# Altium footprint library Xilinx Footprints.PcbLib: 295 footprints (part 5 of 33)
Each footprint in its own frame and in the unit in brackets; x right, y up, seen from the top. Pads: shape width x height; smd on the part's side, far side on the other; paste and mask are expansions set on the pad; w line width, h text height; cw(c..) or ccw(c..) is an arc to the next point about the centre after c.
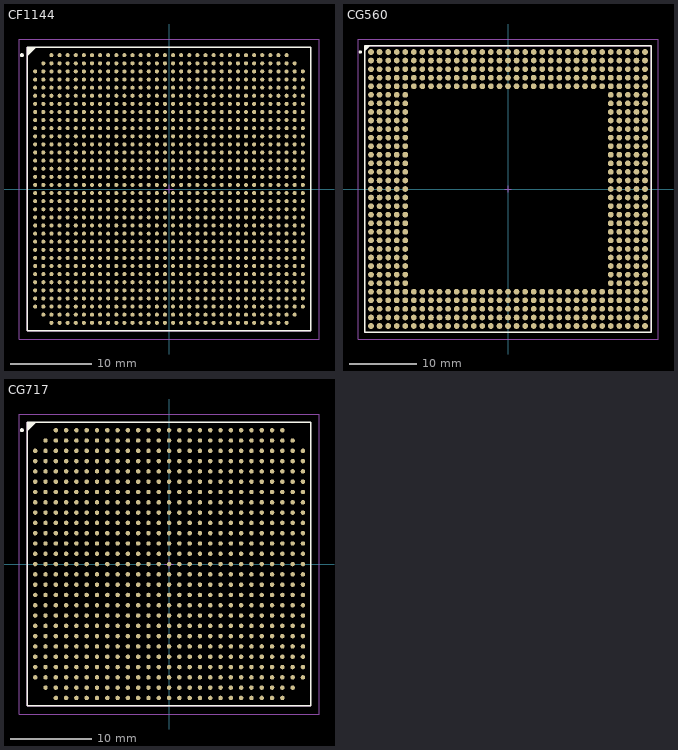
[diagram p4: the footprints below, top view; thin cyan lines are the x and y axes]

## CF1144 [mm] "1156-Pin Ceramic Column Grid Array 1 mm Pitch"
height 7
pads (1144):
  round 0.5 smd: A3(-14.5,16.5) A4(-13.5,16.5) A5(-12.5,16.5) A6(-11.5,16.5) A7(-10.5,16.5) A8(-9.5,16.5) A9(-8.5,16.5) A10(-7.5,16.5) A11(-6.5,16.5) A12(-5.5,16.5) A13(-4.5,16.5) A14(-3.5,16.5) A15(-2.5,16.5) A16(-1.5,16.5) A17(-0.5,16.5) A18(0.5,16.5) A19(1.5,16.5) A20(2.5,16.5) A21(3.5,16.5) A22(4.5,16.5) A23(5.5,16.5) A24(6.5,16.5) A25(7.5,16.5) A26(8.5,16.5) A27(9.5,16.5) A28(10.5,16.5) A29(11.5,16.5) A30(12.5,16.5) A31(13.5,16.5) A32(14.5,16.5) AA1(-16.5,-3.5) AA2(-15.5,-3.5) AA3(-14.5,-3.5) AA4(-13.5,-3.5) AA5(-12.5,-3.5) AA6(-11.5,-3.5) AA7(-10.5,-3.5) AA8(-9.5,-3.5) AA9(-8.5,-3.5) AA10(-7.5,-3.5) AA11(-6.5,-3.5) AA12(-5.5,-3.5) AA13(-4.5,-3.5) AA14(-3.5,-3.5) AA15(-2.5,-3.5) AA16(-1.5,-3.5) AA17(-0.5,-3.5) AA18(0.5,-3.5) AA19(1.5,-3.5) AA20(2.5,-3.5) AA21(3.5,-3.5) AA22(4.5,-3.5) AA23(5.5,-3.5) AA24(6.5,-3.5) AA25(7.5,-3.5) AA26(8.5,-3.5) AA27(9.5,-3.5) AA28(10.5,-3.5) AA29(11.5,-3.5) AA30(12.5,-3.5) AA31(13.5,-3.5) AA32(14.5,-3.5) AA33(15.5,-3.5) AA34(16.5,-3.5) AB1(-16.5,-4.5) AB2(-15.5,-4.5) AB3(-14.5,-4.5) AB4(-13.5,-4.5) AB5(-12.5,-4.5) AB6(-11.5,-4.5) AB7(-10.5,-4.5) AB8(-9.5,-4.5) AB9(-8.5,-4.5) AB10(-7.5,-4.5) AB11(-6.5,-4.5) AB12(-5.5,-4.5) AB13(-4.5,-4.5) AB14(-3.5,-4.5) AB15(-2.5,-4.5) AB16(-1.5,-4.5) AB17(-0.5,-4.5) AB18(0.5,-4.5) AB19(1.5,-4.5) AB20(2.5,-4.5) AB21(3.5,-4.5) AB22(4.5,-4.5) AB23(5.5,-4.5) AB24(6.5,-4.5) AB25(7.5,-4.5) AB26(8.5,-4.5) AB27(9.5,-4.5) AB28(10.5,-4.5) AB29(11.5,-4.5) AB30(12.5,-4.5) AB31(13.5,-4.5) AB32(14.5,-4.5) AB33(15.5,-4.5) AB34(16.5,-4.5) AC1(-16.5,-5.5) AC2(-15.5,-5.5) AC3(-14.5,-5.5) AC4(-13.5,-5.5) AC5(-12.5,-5.5) AC6(-11.5,-5.5) AC7(-10.5,-5.5) AC8(-9.5,-5.5) AC9(-8.5,-5.5) AC10(-7.5,-5.5) AC11(-6.5,-5.5) AC12(-5.5,-5.5) AC13(-4.5,-5.5) AC14(-3.5,-5.5) AC15(-2.5,-5.5) AC16(-1.5,-5.5) AC17(-0.5,-5.5) AC18(0.5,-5.5) AC19(1.5,-5.5) AC20(2.5,-5.5) AC21(3.5,-5.5) AC22(4.5,-5.5) AC23(5.5,-5.5) AC24(6.5,-5.5) AC25(7.5,-5.5) AC26(8.5,-5.5) AC27(9.5,-5.5) AC28(10.5,-5.5) AC29(11.5,-5.5) AC30(12.5,-5.5) AC31(13.5,-5.5) AC32(14.5,-5.5) AC33(15.5,-5.5) AC34(16.5,-5.5) AD1(-16.5,-6.5) AD2(-15.5,-6.5) AD3(-14.5,-6.5) AD4(-13.5,-6.5) AD5(-12.5,-6.5) AD6(-11.5,-6.5) AD7(-10.5,-6.5) AD8(-9.5,-6.5) AD9(-8.5,-6.5) AD10(-7.5,-6.5) AD11(-6.5,-6.5) AD12(-5.5,-6.5) AD13(-4.5,-6.5) AD14(-3.5,-6.5) AD15(-2.5,-6.5) AD16(-1.5,-6.5) AD17(-0.5,-6.5) AD18(0.5,-6.5) AD19(1.5,-6.5) AD20(2.5,-6.5) AD21(3.5,-6.5) AD22(4.5,-6.5) AD23(5.5,-6.5) AD24(6.5,-6.5) AD25(7.5,-6.5) AD26(8.5,-6.5) AD27(9.5,-6.5) AD28(10.5,-6.5) AD29(11.5,-6.5) AD30(12.5,-6.5) AD31(13.5,-6.5) AD32(14.5,-6.5) AD33(15.5,-6.5) AD34(16.5,-6.5) AE1(-16.5,-7.5) AE2(-15.5,-7.5) AE3(-14.5,-7.5) AE4(-13.5,-7.5) AE5(-12.5,-7.5) AE6(-11.5,-7.5) AE7(-10.5,-7.5) AE8(-9.5,-7.5) AE9(-8.5,-7.5) AE10(-7.5,-7.5) AE11(-6.5,-7.5) AE12(-5.5,-7.5) AE13(-4.5,-7.5) AE14(-3.5,-7.5) AE15(-2.5,-7.5) AE16(-1.5,-7.5) AE17(-0.5,-7.5) AE18(0.5,-7.5) AE19(1.5,-7.5) AE20(2.5,-7.5) AE21(3.5,-7.5) AE22(4.5,-7.5) AE23(5.5,-7.5) AE24(6.5,-7.5) AE25(7.5,-7.5) AE26(8.5,-7.5) AE27(9.5,-7.5) AE28(10.5,-7.5) AE29(11.5,-7.5) AE30(12.5,-7.5) AE31(13.5,-7.5) AE32(14.5,-7.5) AE33(15.5,-7.5) AE34(16.5,-7.5) AF1(-16.5,-8.5) AF2(-15.5,-8.5) AF3(-14.5,-8.5) AF4(-13.5,-8.5) AF5(-12.5,-8.5) AF6(-11.5,-8.5) AF7(-10.5,-8.5) AF8(-9.5,-8.5) AF9(-8.5,-8.5) AF10(-7.5,-8.5) AF11(-6.5,-8.5) AF12(-5.5,-8.5) AF13(-4.5,-8.5) AF14(-3.5,-8.5) AF15(-2.5,-8.5) AF16(-1.5,-8.5) AF17(-0.5,-8.5) AF18(0.5,-8.5) AF19(1.5,-8.5) AF20(2.5,-8.5) AF21(3.5,-8.5) AF22(4.5,-8.5) AF23(5.5,-8.5) AF24(6.5,-8.5) AF25(7.5,-8.5) AF26(8.5,-8.5) AF27(9.5,-8.5) AF28(10.5,-8.5) AF29(11.5,-8.5) AF30(12.5,-8.5) AF31(13.5,-8.5) AF32(14.5,-8.5) AF33(15.5,-8.5) AF34(16.5,-8.5) AG1(-16.5,-9.5) AG2(-15.5,-9.5) AG3(-14.5,-9.5) AG4(-13.5,-9.5) AG5(-12.5,-9.5) AG6(-11.5,-9.5) AG7(-10.5,-9.5) AG8(-9.5,-9.5) AG9(-8.5,-9.5) AG10(-7.5,-9.5) AG11(-6.5,-9.5) AG12(-5.5,-9.5) AG13(-4.5,-9.5) AG14(-3.5,-9.5) AG15(-2.5,-9.5) AG16(-1.5,-9.5) AG17(-0.5,-9.5) AG18(0.5,-9.5) AG19(1.5,-9.5) AG20(2.5,-9.5) AG21(3.5,-9.5) AG22(4.5,-9.5) AG23(5.5,-9.5) AG24(6.5,-9.5) AG25(7.5,-9.5) AG26(8.5,-9.5) AG27(9.5,-9.5) AG28(10.5,-9.5) AG29(11.5,-9.5) AG30(12.5,-9.5) AG31(13.5,-9.5) AG32(14.5,-9.5) AG33(15.5,-9.5) AG34(16.5,-9.5) AH1(-16.5,-10.5) AH2(-15.5,-10.5) AH3(-14.5,-10.5) AH4(-13.5,-10.5) AH5(-12.5,-10.5) AH6(-11.5,-10.5) AH7(-10.5,-10.5) AH8(-9.5,-10.5) AH9(-8.5,-10.5) AH10(-7.5,-10.5) AH11(-6.5,-10.5) AH12(-5.5,-10.5) AH13(-4.5,-10.5) AH14(-3.5,-10.5) AH15(-2.5,-10.5) AH16(-1.5,-10.5) AH17(-0.5,-10.5) AH18(0.5,-10.5) AH19(1.5,-10.5) AH20(2.5,-10.5) AH21(3.5,-10.5) AH22(4.5,-10.5) AH23(5.5,-10.5) AH24(6.5,-10.5) AH25(7.5,-10.5) AH26(8.5,-10.5) AH27(9.5,-10.5) AH28(10.5,-10.5) AH29(11.5,-10.5) AH30(12.5,-10.5) AH31(13.5,-10.5) AH32(14.5,-10.5) AH33(15.5,-10.5) AH34(16.5,-10.5) AJ1(-16.5,-11.5) AJ2(-15.5,-11.5) AJ3(-14.5,-11.5) AJ4(-13.5,-11.5) AJ5(-12.5,-11.5) AJ6(-11.5,-11.5) AJ7(-10.5,-11.5) AJ8(-9.5,-11.5) AJ9(-8.5,-11.5) AJ10(-7.5,-11.5) AJ11(-6.5,-11.5) AJ12(-5.5,-11.5) AJ13(-4.5,-11.5) AJ14(-3.5,-11.5) AJ15(-2.5,-11.5) AJ16(-1.5,-11.5) AJ17(-0.5,-11.5) AJ18(0.5,-11.5) AJ19(1.5,-11.5) AJ20(2.5,-11.5) AJ21(3.5,-11.5) AJ22(4.5,-11.5) AJ23(5.5,-11.5) AJ24(6.5,-11.5) AJ25(7.5,-11.5) AJ26(8.5,-11.5) AJ27(9.5,-11.5) AJ28(10.5,-11.5) AJ29(11.5,-11.5) AJ30(12.5,-11.5) AJ31(13.5,-11.5) AJ32(14.5,-11.5) AJ33(15.5,-11.5) AJ34(16.5,-11.5) AK1(-16.5,-12.5) AK2(-15.5,-12.5) AK3(-14.5,-12.5) AK4(-13.5,-12.5) AK5(-12.5,-12.5) AK6(-11.5,-12.5) AK7(-10.5,-12.5) AK8(-9.5,-12.5) AK9(-8.5,-12.5) AK10(-7.5,-12.5) AK11(-6.5,-12.5) AK12(-5.5,-12.5) AK13(-4.5,-12.5) AK14(-3.5,-12.5) AK15(-2.5,-12.5) AK16(-1.5,-12.5) AK17(-0.5,-12.5) AK18(0.5,-12.5) AK19(1.5,-12.5) AK20(2.5,-12.5) AK21(3.5,-12.5) AK22(4.5,-12.5) AK23(5.5,-12.5) AK24(6.5,-12.5) AK25(7.5,-12.5) AK26(8.5,-12.5) AK27(9.5,-12.5) AK28(10.5,-12.5) AK29(11.5,-12.5) AK30(12.5,-12.5) AK31(13.5,-12.5) AK32(14.5,-12.5) AK33(15.5,-12.5) AK34(16.5,-12.5) AL1(-16.5,-13.5) AL2(-15.5,-13.5) AL3(-14.5,-13.5) AL4(-13.5,-13.5) AL5(-12.5,-13.5) AL6(-11.5,-13.5) AL7(-10.5,-13.5) AL8(-9.5,-13.5) AL9(-8.5,-13.5) AL10(-7.5,-13.5) AL11(-6.5,-13.5) AL12(-5.5,-13.5) AL13(-4.5,-13.5) AL14(-3.5,-13.5) AL15(-2.5,-13.5) AL16(-1.5,-13.5) AL17(-0.5,-13.5) AL18(0.5,-13.5) AL19(1.5,-13.5) AL20(2.5,-13.5) AL21(3.5,-13.5) AL22(4.5,-13.5) AL23(5.5,-13.5) AL24(6.5,-13.5) AL25(7.5,-13.5) AL26(8.5,-13.5) AL27(9.5,-13.5) AL28(10.5,-13.5) AL29(11.5,-13.5) AL30(12.5,-13.5) AL31(13.5,-13.5) AL32(14.5,-13.5) AL33(15.5,-13.5) AL34(16.5,-13.5) AM1(-16.5,-14.5) AM2(-15.5,-14.5) AM3(-14.5,-14.5) AM4(-13.5,-14.5) AM5(-12.5,-14.5) AM6(-11.5,-14.5) AM7(-10.5,-14.5) AM8(-9.5,-14.5) AM9(-8.5,-14.5) AM10(-7.5,-14.5) AM11(-6.5,-14.5) AM12(-5.5,-14.5) AM13(-4.5,-14.5) AM14(-3.5,-14.5) AM15(-2.5,-14.5) AM16(-1.5,-14.5) AM17(-0.5,-14.5) AM18(0.5,-14.5) AM19(1.5,-14.5) AM20(2.5,-14.5) AM21(3.5,-14.5) AM22(4.5,-14.5) AM23(5.5,-14.5) AM24(6.5,-14.5) AM25(7.5,-14.5) AM26(8.5,-14.5) AM27(9.5,-14.5) AM28(10.5,-14.5) AM29(11.5,-14.5) AM30(12.5,-14.5) AM31(13.5,-14.5) AM32(14.5,-14.5) AM33(15.5,-14.5) AM34(16.5,-14.5) AN2(-15.5,-15.5) AN3(-14.5,-15.5) AN4(-13.5,-15.5) AN5(-12.5,-15.5) AN6(-11.5,-15.5) AN7(-10.5,-15.5) AN8(-9.5,-15.5) AN9(-8.5,-15.5) AN10(-7.5,-15.5) AN11(-6.5,-15.5) AN12(-5.5,-15.5) AN13(-4.5,-15.5) AN14(-3.5,-15.5) AN15(-2.5,-15.5) AN16(-1.5,-15.5) AN17(-0.5,-15.5) AN18(0.5,-15.5) AN19(1.5,-15.5) AN20(2.5,-15.5) AN21(3.5,-15.5) AN22(4.5,-15.5) AN23(5.5,-15.5) AN24(6.5,-15.5) AN25(7.5,-15.5) AN26(8.5,-15.5) AN27(9.5,-15.5) AN28(10.5,-15.5) AN29(11.5,-15.5) AN30(12.5,-15.5) AN31(13.5,-15.5) AN32(14.5,-15.5) AN33(15.5,-15.5) AP3(-14.5,-16.5) AP4(-13.5,-16.5) AP5(-12.5,-16.5) AP6(-11.5,-16.5) AP7(-10.5,-16.5) AP8(-9.5,-16.5) AP9(-8.5,-16.5) AP10(-7.5,-16.5) AP11(-6.5,-16.5) AP12(-5.5,-16.5) AP13(-4.5,-16.5) AP14(-3.5,-16.5) AP15(-2.5,-16.5) AP16(-1.5,-16.5) AP17(-0.5,-16.5) AP18(0.5,-16.5) AP19(1.5,-16.5) AP20(2.5,-16.5) AP21(3.5,-16.5) AP22(4.5,-16.5) AP23(5.5,-16.5) AP24(6.5,-16.5) AP25(7.5,-16.5) AP26(8.5,-16.5) AP27(9.5,-16.5) AP28(10.5,-16.5) AP29(11.5,-16.5) AP30(12.5,-16.5) AP31(13.5,-16.5) AP32(14.5,-16.5) B2(-15.5,15.5) B3(-14.5,15.5) B4(-13.5,15.5) B5(-12.5,15.5) B6(-11.5,15.5) B7(-10.5,15.5) B8(-9.5,15.5) B9(-8.5,15.5) B10(-7.5,15.5) B11(-6.5,15.5) B12(-5.5,15.5) B13(-4.5,15.5) B14(-3.5,15.5) B15(-2.5,15.5) B16(-1.5,15.5) B17(-0.5,15.5) B18(0.5,15.5) B19(1.5,15.5) B20(2.5,15.5) B21(3.5,15.5) B22(4.5,15.5) B23(5.5,15.5) B24(6.5,15.5) B25(7.5,15.5) B26(8.5,15.5) B27(9.5,15.5) B28(10.5,15.5) B29(11.5,15.5) B30(12.5,15.5) B31(13.5,15.5) B32(14.5,15.5) B33(15.5,15.5) C1(-16.5,14.5) C2(-15.5,14.5) C3(-14.5,14.5) C4(-13.5,14.5) C5(-12.5,14.5) C6(-11.5,14.5) C7(-10.5,14.5) C8(-9.5,14.5) C9(-8.5,14.5) C10(-7.5,14.5) C11(-6.5,14.5) C12(-5.5,14.5) C13(-4.5,14.5) C14(-3.5,14.5) C15(-2.5,14.5) C16(-1.5,14.5) C17(-0.5,14.5) C18(0.5,14.5) C19(1.5,14.5) C20(2.5,14.5) C21(3.5,14.5) C22(4.5,14.5) C23(5.5,14.5) C24(6.5,14.5) C25(7.5,14.5) C26(8.5,14.5) C27(9.5,14.5) C28(10.5,14.5) C29(11.5,14.5) C30(12.5,14.5) C31(13.5,14.5) C32(14.5,14.5) C33(15.5,14.5) C34(16.5,14.5) D1(-16.5,13.5) D2(-15.5,13.5) D3(-14.5,13.5) D4(-13.5,13.5) D5(-12.5,13.5) D6(-11.5,13.5) D7(-10.5,13.5) D8(-9.5,13.5) D9(-8.5,13.5) D10(-7.5,13.5) D11(-6.5,13.5) D12(-5.5,13.5) D13(-4.5,13.5) D14(-3.5,13.5) D15(-2.5,13.5) D16(-1.5,13.5) D17(-0.5,13.5) D18(0.5,13.5) D19(1.5,13.5) D20(2.5,13.5) D21(3.5,13.5) D22(4.5,13.5) D23(5.5,13.5) D24(6.5,13.5) D25(7.5,13.5) D26(8.5,13.5) D27(9.5,13.5) D28(10.5,13.5) D29(11.5,13.5) D30(12.5,13.5) D31(13.5,13.5) D32(14.5,13.5) D33(15.5,13.5) D34(16.5,13.5) E1(-16.5,12.5) E2(-15.5,12.5) E3(-14.5,12.5) E4(-13.5,12.5) E5(-12.5,12.5) E6(-11.5,12.5) E7(-10.5,12.5) E8(-9.5,12.5) E9(-8.5,12.5) E10(-7.5,12.5) E11(-6.5,12.5) E12(-5.5,12.5) E13(-4.5,12.5) E14(-3.5,12.5) E15(-2.5,12.5) E16(-1.5,12.5) E17(-0.5,12.5) E18(0.5,12.5) E19(1.5,12.5) E20(2.5,12.5) E21(3.5,12.5) E22(4.5,12.5) E23(5.5,12.5) E24(6.5,12.5) E25(7.5,12.5) E26(8.5,12.5) E27(9.5,12.5) E28(10.5,12.5) E29(11.5,12.5) E30(12.5,12.5) E31(13.5,12.5) E32(14.5,12.5) E33(15.5,12.5) E34(16.5,12.5) F1(-16.5,11.5) F2(-15.5,11.5) F3(-14.5,11.5) F4(-13.5,11.5) F5(-12.5,11.5) F6(-11.5,11.5) F7(-10.5,11.5) F8(-9.5,11.5) F9(-8.5,11.5) F10(-7.5,11.5) F11(-6.5,11.5) F12(-5.5,11.5) F13(-4.5,11.5) F14(-3.5,11.5) F15(-2.5,11.5) F16(-1.5,11.5) F17(-0.5,11.5) F18(0.5,11.5) F19(1.5,11.5) F20(2.5,11.5) F21(3.5,11.5) F22(4.5,11.5) F23(5.5,11.5) F24(6.5,11.5) F25(7.5,11.5) F26(8.5,11.5) F27(9.5,11.5) F28(10.5,11.5) F29(11.5,11.5) F30(12.5,11.5) F31(13.5,11.5) F32(14.5,11.5) F33(15.5,11.5) F34(16.5,11.5) G1(-16.5,10.5) G2(-15.5,10.5) G3(-14.5,10.5) G4(-13.5,10.5) G5(-12.5,10.5) G6(-11.5,10.5) G7(-10.5,10.5) G8(-9.5,10.5) G9(-8.5,10.5) G10(-7.5,10.5) G11(-6.5,10.5) G12(-5.5,10.5) G13(-4.5,10.5) G14(-3.5,10.5) G15(-2.5,10.5) G16(-1.5,10.5) G17(-0.5,10.5) G18(0.5,10.5) G19(1.5,10.5) G20(2.5,10.5) G21(3.5,10.5) G22(4.5,10.5) G23(5.5,10.5) G24(6.5,10.5) G25(7.5,10.5) G26(8.5,10.5) G27(9.5,10.5) G28(10.5,10.5) G29(11.5,10.5) G30(12.5,10.5) G31(13.5,10.5) G32(14.5,10.5) G33(15.5,10.5) G34(16.5,10.5) H1(-16.5,9.5) H2(-15.5,9.5) H3(-14.5,9.5) H4(-13.5,9.5) H5(-12.5,9.5) H6(-11.5,9.5) H7(-10.5,9.5) H8(-9.5,9.5) H9(-8.5,9.5) H10(-7.5,9.5) H11(-6.5,9.5) H12(-5.5,9.5) H13(-4.5,9.5) H14(-3.5,9.5) H15(-2.5,9.5) H16(-1.5,9.5) H17(-0.5,9.5) H18(0.5,9.5) H19(1.5,9.5) H20(2.5,9.5) H21(3.5,9.5) H22(4.5,9.5) H23(5.5,9.5) H24(6.5,9.5) H25(7.5,9.5) H26(8.5,9.5) H27(9.5,9.5) H28(10.5,9.5) H29(11.5,9.5) H30(12.5,9.5) H31(13.5,9.5) H32(14.5,9.5) H33(15.5,9.5) H34(16.5,9.5) J1(-16.5,8.5) J2(-15.5,8.5) J3(-14.5,8.5) J4(-13.5,8.5) J5(-12.5,8.5) J6(-11.5,8.5) J7(-10.5,8.5) J8(-9.5,8.5) J9(-8.5,8.5) J10(-7.5,8.5) J11(-6.5,8.5) J12(-5.5,8.5) J13(-4.5,8.5) J14(-3.5,8.5) J15(-2.5,8.5) J16(-1.5,8.5) J17(-0.5,8.5) J18(0.5,8.5) J19(1.5,8.5) J20(2.5,8.5) J21(3.5,8.5) J22(4.5,8.5) J23(5.5,8.5) J24(6.5,8.5) J25(7.5,8.5) J26(8.5,8.5) J27(9.5,8.5) J28(10.5,8.5) J29(11.5,8.5) J30(12.5,8.5) J31(13.5,8.5) J32(14.5,8.5) J33(15.5,8.5) J34(16.5,8.5) K1(-16.5,7.5) K2(-15.5,7.5) K3(-14.5,7.5) K4(-13.5,7.5) K5(-12.5,7.5) K6(-11.5,7.5) K7(-10.5,7.5) K8(-9.5,7.5) K9(-8.5,7.5) K10(-7.5,7.5) K11(-6.5,7.5) K12(-5.5,7.5) K13(-4.5,7.5) K14(-3.5,7.5) K15(-2.5,7.5) K16(-1.5,7.5) K17(-0.5,7.5) K18(0.5,7.5) K19(1.5,7.5) K20(2.5,7.5) K21(3.5,7.5) K22(4.5,7.5) K23(5.5,7.5) K24(6.5,7.5) K25(7.5,7.5) K26(8.5,7.5) K27(9.5,7.5) K28(10.5,7.5) K29(11.5,7.5) K30(12.5,7.5) K31(13.5,7.5) K32(14.5,7.5) K33(15.5,7.5) K34(16.5,7.5) L1(-16.5,6.5) L2(-15.5,6.5) L3(-14.5,6.5) L4(-13.5,6.5) L5(-12.5,6.5) L6(-11.5,6.5) L7(-10.5,6.5) L8(-9.5,6.5) L9(-8.5,6.5) L10(-7.5,6.5) L11(-6.5,6.5) L12(-5.5,6.5) L13(-4.5,6.5) L14(-3.5,6.5) L15(-2.5,6.5) L16(-1.5,6.5) L17(-0.5,6.5) L18(0.5,6.5) L19(1.5,6.5) L20(2.5,6.5) L21(3.5,6.5) L22(4.5,6.5) L23(5.5,6.5) L24(6.5,6.5) L25(7.5,6.5) L26(8.5,6.5) L27(9.5,6.5) L28(10.5,6.5) L29(11.5,6.5) L30(12.5,6.5) L31(13.5,6.5) L32(14.5,6.5) L33(15.5,6.5) L34(16.5,6.5) M1(-16.5,5.5) M2(-15.5,5.5) M3(-14.5,5.5) M4(-13.5,5.5) M5(-12.5,5.5) M6(-11.5,5.5) M7(-10.5,5.5) M8(-9.5,5.5) M9(-8.5,5.5) M10(-7.5,5.5) M11(-6.5,5.5) M12(-5.5,5.5) M13(-4.5,5.5) M14(-3.5,5.5) M15(-2.5,5.5) M16(-1.5,5.5) M17(-0.5,5.5) M18(0.5,5.5) M19(1.5,5.5) M20(2.5,5.5) M21(3.5,5.5) M22(4.5,5.5) M23(5.5,5.5) M24(6.5,5.5) M25(7.5,5.5) M26(8.5,5.5) M27(9.5,5.5) M28(10.5,5.5) M29(11.5,5.5) M30(12.5,5.5) M31(13.5,5.5) M32(14.5,5.5) M33(15.5,5.5) M34(16.5,5.5) N1(-16.5,4.5) N2(-15.5,4.5) N3(-14.5,4.5) N4(-13.5,4.5) N5(-12.5,4.5) N6(-11.5,4.5) N7(-10.5,4.5) N8(-9.5,4.5) N9(-8.5,4.5) N10(-7.5,4.5) N11(-6.5,4.5) N12(-5.5,4.5) N13(-4.5,4.5) N14(-3.5,4.5) N15(-2.5,4.5) N16(-1.5,4.5) N17(-0.5,4.5) N18(0.5,4.5) N19(1.5,4.5) N20(2.5,4.5) N21(3.5,4.5) N22(4.5,4.5) N23(5.5,4.5) N24(6.5,4.5) N25(7.5,4.5) N26(8.5,4.5) N27(9.5,4.5) N28(10.5,4.5) N29(11.5,4.5) N30(12.5,4.5) N31(13.5,4.5) N32(14.5,4.5) N33(15.5,4.5) N34(16.5,4.5) P1(-16.5,3.5) P2(-15.5,3.5) P3(-14.5,3.5) P4(-13.5,3.5) P5(-12.5,3.5) P6(-11.5,3.5) P7(-10.5,3.5) P8(-9.5,3.5) P9(-8.5,3.5) P10(-7.5,3.5) P11(-6.5,3.5) P12(-5.5,3.5) P13(-4.5,3.5) P14(-3.5,3.5) P15(-2.5,3.5) P16(-1.5,3.5) P17(-0.5,3.5) P18(0.5,3.5) P19(1.5,3.5) P20(2.5,3.5) P21(3.5,3.5) P22(4.5,3.5) P23(5.5,3.5) P24(6.5,3.5) P25(7.5,3.5) P26(8.5,3.5) P27(9.5,3.5) P28(10.5,3.5) P29(11.5,3.5) P30(12.5,3.5) P31(13.5,3.5) P32(14.5,3.5) P33(15.5,3.5) P34(16.5,3.5) R1(-16.5,2.5) R2(-15.5,2.5) R3(-14.5,2.5) R4(-13.5,2.5) R5(-12.5,2.5) R6(-11.5,2.5) R7(-10.5,2.5) R8(-9.5,2.5) R9(-8.5,2.5) R10(-7.5,2.5) R11(-6.5,2.5) R12(-5.5,2.5) R13(-4.5,2.5) R14(-3.5,2.5) R15(-2.5,2.5) R16(-1.5,2.5) R17(-0.5,2.5) R18(0.5,2.5) R19(1.5,2.5) R20(2.5,2.5) R21(3.5,2.5) R22(4.5,2.5) R23(5.5,2.5) R24(6.5,2.5) R25(7.5,2.5) R26(8.5,2.5) R27(9.5,2.5) R28(10.5,2.5) R29(11.5,2.5) R30(12.5,2.5) R31(13.5,2.5) R32(14.5,2.5) R33(15.5,2.5) R34(16.5,2.5) T1(-16.5,1.5) T2(-15.5,1.5) T3(-14.5,1.5) T4(-13.5,1.5) T5(-12.5,1.5) T6(-11.5,1.5) T7(-10.5,1.5) T8(-9.5,1.5) T9(-8.5,1.5) T10(-7.5,1.5) T11(-6.5,1.5) T12(-5.5,1.5) T13(-4.5,1.5) T14(-3.5,1.5) T15(-2.5,1.5) T16(-1.5,1.5) T17(-0.5,1.5) T18(0.5,1.5) T19(1.5,1.5) T20(2.5,1.5) T21(3.5,1.5) T22(4.5,1.5) T23(5.5,1.5) T24(6.5,1.5) T25(7.5,1.5) T26(8.5,1.5) T27(9.5,1.5) T28(10.5,1.5) T29(11.5,1.5) T30(12.5,1.5) T31(13.5,1.5) T32(14.5,1.5) T33(15.5,1.5) T34(16.5,1.5) U1(-16.5,0.5) U2(-15.5,0.5) U3(-14.5,0.5) U4(-13.5,0.5) U5(-12.5,0.5) U6(-11.5,0.5) U7(-10.5,0.5) U8(-9.5,0.5) U9(-8.5,0.5) U10(-7.5,0.5) U11(-6.5,0.5) U12(-5.5,0.5) U13(-4.5,0.5) U14(-3.5,0.5) U15(-2.5,0.5) U16(-1.5,0.5) U17(-0.5,0.5) U18(0.5,0.5) U19(1.5,0.5) U20(2.5,0.5) U21(3.5,0.5) U22(4.5,0.5) U23(5.5,0.5) U24(6.5,0.5) U25(7.5,0.5) U26(8.5,0.5) U27(9.5,0.5) U28(10.5,0.5) U29(11.5,0.5) U30(12.5,0.5) U31(13.5,0.5) U32(14.5,0.5) U33(15.5,0.5) U34(16.5,0.5) V1(-16.5,-0.5) V2(-15.5,-0.5) V3(-14.5,-0.5) V4(-13.5,-0.5) V5(-12.5,-0.5) V6(-11.5,-0.5) V7(-10.5,-0.5) V8(-9.5,-0.5) V9(-8.5,-0.5) V10(-7.5,-0.5) V11(-6.5,-0.5) V12(-5.5,-0.5) V13(-4.5,-0.5) V14(-3.5,-0.5) V15(-2.5,-0.5) V16(-1.5,-0.5) V17(-0.5,-0.5) V18(0.5,-0.5) V19(1.5,-0.5) V20(2.5,-0.5) V21(3.5,-0.5) V22(4.5,-0.5) V23(5.5,-0.5) V24(6.5,-0.5) V25(7.5,-0.5) V26(8.5,-0.5) V27(9.5,-0.5) V28(10.5,-0.5) V29(11.5,-0.5) V30(12.5,-0.5) V31(13.5,-0.5) V32(14.5,-0.5) V33(15.5,-0.5) V34(16.5,-0.5) W1(-16.5,-1.5) W2(-15.5,-1.5) W3(-14.5,-1.5) W4(-13.5,-1.5) W5(-12.5,-1.5) W6(-11.5,-1.5) W7(-10.5,-1.5) W8(-9.5,-1.5) W9(-8.5,-1.5) W10(-7.5,-1.5) W11(-6.5,-1.5) W12(-5.5,-1.5) W13(-4.5,-1.5) W14(-3.5,-1.5) W15(-2.5,-1.5) W16(-1.5,-1.5) W17(-0.5,-1.5) W18(0.5,-1.5) W19(1.5,-1.5) W20(2.5,-1.5) W21(3.5,-1.5) W22(4.5,-1.5) W23(5.5,-1.5) W24(6.5,-1.5) W25(7.5,-1.5) W26(8.5,-1.5) W27(9.5,-1.5) W28(10.5,-1.5) W29(11.5,-1.5) W30(12.5,-1.5) W31(13.5,-1.5) W32(14.5,-1.5) W33(15.5,-1.5) W34(16.5,-1.5) Y1(-16.5,-2.5) Y2(-15.5,-2.5) Y3(-14.5,-2.5) Y4(-13.5,-2.5) Y5(-12.5,-2.5) Y6(-11.5,-2.5) Y7(-10.5,-2.5) Y8(-9.5,-2.5) Y9(-8.5,-2.5) Y10(-7.5,-2.5) Y11(-6.5,-2.5) Y12(-5.5,-2.5) Y13(-4.5,-2.5) Y14(-3.5,-2.5) Y15(-2.5,-2.5) Y16(-1.5,-2.5) Y17(-0.5,-2.5) Y18(0.5,-2.5) Y19(1.5,-2.5) Y20(2.5,-2.5) Y21(3.5,-2.5) Y22(4.5,-2.5) Y23(5.5,-2.5) Y24(6.5,-2.5) Y25(7.5,-2.5) Y26(8.5,-2.5) Y27(9.5,-2.5) Y28(10.5,-2.5) Y29(11.5,-2.5) Y30(12.5,-2.5) Y31(13.5,-2.5) Y32(14.5,-2.5) Y33(15.5,-2.5) Y34(16.5,-2.5)
Top Overlay:
  circle w0.25: c-18.15,16.5 r0.125
  region: -16.5,17.5 -17.5,16.5 -17.5,17.5
  lines w0.2: -17.5,16.5 -16.5,17.5 ; -17.5,-17.5 -17.5,17.5 17.5,17.5 17.5,-17.5 -17.5,-17.5
Mechanical 13:
  lines w0.1: -17.5,-17.5 -17.5,17.5 17.5,17.5 17.5,-17.5 -17.5,-17.5
Mechanical 15:
  lines w0.1: -0.5,0 0.5,0 ; 0,-0.5 0,0.5 ; -18.5,-18.5 -18.5,18.5 18.5,18.5 18.5,-18.5 -18.5,-18.5
3D body: height 7, standoff 0, extent -17.5,-17.5 17.5,17.5

## CG560 [mm] "1089-Pin Ceramic Column Grid Array 1.27 mm Pitch"
height 5.35
pads (560):
  round 0.85 smd: A1(-20.32,20.32) A2(-19.05,20.32) A3(-17.78,20.32) A4(-16.51,20.32) A5(-15.24,20.32) A6(-13.97,20.32) A7(-12.7,20.32) A8(-11.43,20.32) A9(-10.16,20.32) A10(-8.89,20.32) A11(-7.62,20.32) A12(-6.35,20.32) A13(-5.08,20.32) A14(-3.81,20.32) A15(-2.54,20.32) A16(-1.27,20.32) A17(0,20.32) A18(1.27,20.32) A19(2.54,20.32) A20(3.81,20.32) A21(5.08,20.32) A22(6.35,20.32) A23(7.62,20.32) A24(8.89,20.32) A25(10.16,20.32) A26(11.43,20.32) A27(12.7,20.32) A28(13.97,20.32) A29(15.24,20.32) A30(16.51,20.32) A31(17.78,20.32) A32(19.05,20.32) A33(20.32,20.32) AA1(-20.32,-5.08) AA2(-19.05,-5.08) AA3(-17.78,-5.08) AA4(-16.51,-5.08) AA5(-15.24,-5.08) AA29(15.24,-5.08) AA30(16.51,-5.08) AA31(17.78,-5.08) AA32(19.05,-5.08) AA33(20.32,-5.08) AB1(-20.32,-6.35) AB2(-19.05,-6.35) AB3(-17.78,-6.35) AB4(-16.51,-6.35) AB5(-15.24,-6.35) AB29(15.24,-6.35) AB30(16.51,-6.35) AB31(17.78,-6.35) AB32(19.05,-6.35) AB33(20.32,-6.35) AC1(-20.32,-7.62) AC2(-19.05,-7.62) AC3(-17.78,-7.62) AC4(-16.51,-7.62) AC5(-15.24,-7.62) AC29(15.24,-7.62) AC30(16.51,-7.62) AC31(17.78,-7.62) AC32(19.05,-7.62) AC33(20.32,-7.62) AD1(-20.32,-8.89) AD2(-19.05,-8.89) AD3(-17.78,-8.89) AD4(-16.51,-8.89) AD5(-15.24,-8.89) AD29(15.24,-8.89) AD30(16.51,-8.89) AD31(17.78,-8.89) AD32(19.05,-8.89) AD33(20.32,-8.89) AE1(-20.32,-10.16) AE2(-19.05,-10.16) AE3(-17.78,-10.16) AE4(-16.51,-10.16) AE5(-15.24,-10.16) AE29(15.24,-10.16) AE30(16.51,-10.16) AE31(17.78,-10.16) AE32(19.05,-10.16) AE33(20.32,-10.16) AF1(-20.32,-11.43) AF2(-19.05,-11.43) AF3(-17.78,-11.43) AF4(-16.51,-11.43) AF5(-15.24,-11.43) AF29(15.24,-11.43) AF30(16.51,-11.43) AF31(17.78,-11.43) AF32(19.05,-11.43) AF33(20.32,-11.43) AG1(-20.32,-12.7) AG2(-19.05,-12.7) AG3(-17.78,-12.7) AG4(-16.51,-12.7) AG5(-15.24,-12.7) AG29(15.24,-12.7) AG30(16.51,-12.7) AG31(17.78,-12.7) AG32(19.05,-12.7) AG33(20.32,-12.7) AH1(-20.32,-13.97) AH2(-19.05,-13.97) AH3(-17.78,-13.97) AH4(-16.51,-13.97) AH5(-15.24,-13.97) AH29(15.24,-13.97) AH30(16.51,-13.97) AH31(17.78,-13.97) AH32(19.05,-13.97) AH33(20.32,-13.97) AJ1(-20.32,-15.24) AJ2(-19.05,-15.24) AJ3(-17.78,-15.24) AJ4(-16.51,-15.24) AJ5(-15.24,-15.24) AJ6(-13.97,-15.24) AJ7(-12.7,-15.24) AJ8(-11.43,-15.24) AJ9(-10.16,-15.24) AJ10(-8.89,-15.24) AJ11(-7.62,-15.24) AJ12(-6.35,-15.24) AJ13(-5.08,-15.24) AJ14(-3.81,-15.24) AJ15(-2.54,-15.24) AJ16(-1.27,-15.24) AJ17(0,-15.24) AJ18(1.27,-15.24) AJ19(2.54,-15.24) AJ20(3.81,-15.24) AJ21(5.08,-15.24) AJ22(6.35,-15.24) AJ23(7.62,-15.24) AJ24(8.89,-15.24) AJ25(10.16,-15.24) AJ26(11.43,-15.24) AJ27(12.7,-15.24) AJ28(13.97,-15.24) AJ29(15.24,-15.24) AJ30(16.51,-15.24) AJ31(17.78,-15.24) AJ32(19.05,-15.24) AJ33(20.32,-15.24) AK1(-20.32,-16.51) AK2(-19.05,-16.51) AK3(-17.78,-16.51) AK4(-16.51,-16.51) AK5(-15.24,-16.51) AK6(-13.97,-16.51) AK7(-12.7,-16.51) AK8(-11.43,-16.51) AK9(-10.16,-16.51) AK10(-8.89,-16.51) AK11(-7.62,-16.51) AK12(-6.35,-16.51) AK13(-5.08,-16.51) AK14(-3.81,-16.51) AK15(-2.54,-16.51) AK16(-1.27,-16.51) AK17(0,-16.51) AK18(1.27,-16.51) AK19(2.54,-16.51) AK20(3.81,-16.51) AK21(5.08,-16.51) AK22(6.35,-16.51) AK23(7.62,-16.51) AK24(8.89,-16.51) AK25(10.16,-16.51) AK26(11.43,-16.51) AK27(12.7,-16.51) AK28(13.97,-16.51) AK29(15.24,-16.51) AK30(16.51,-16.51) AK31(17.78,-16.51) AK32(19.05,-16.51) AK33(20.32,-16.51) AL1(-20.32,-17.78) AL2(-19.05,-17.78) AL3(-17.78,-17.78) AL4(-16.51,-17.78) AL5(-15.24,-17.78) AL6(-13.97,-17.78) AL7(-12.7,-17.78) AL8(-11.43,-17.78) AL9(-10.16,-17.78) AL10(-8.89,-17.78) AL11(-7.62,-17.78) AL12(-6.35,-17.78) AL13(-5.08,-17.78) AL14(-3.81,-17.78) AL15(-2.54,-17.78) AL16(-1.27,-17.78) AL17(0,-17.78) AL18(1.27,-17.78) AL19(2.54,-17.78) AL20(3.81,-17.78) AL21(5.08,-17.78) AL22(6.35,-17.78) AL23(7.62,-17.78) AL24(8.89,-17.78) AL25(10.16,-17.78) AL26(11.43,-17.78) AL27(12.7,-17.78) AL28(13.97,-17.78) AL29(15.24,-17.78) AL30(16.51,-17.78) AL31(17.78,-17.78) AL32(19.05,-17.78) AL33(20.32,-17.78) AM1(-20.32,-19.05) AM2(-19.05,-19.05) AM3(-17.78,-19.05) AM4(-16.51,-19.05) AM5(-15.24,-19.05) AM6(-13.97,-19.05) AM7(-12.7,-19.05) AM8(-11.43,-19.05) AM9(-10.16,-19.05) AM10(-8.89,-19.05) AM11(-7.62,-19.05) AM12(-6.35,-19.05) AM13(-5.08,-19.05) AM14(-3.81,-19.05) AM15(-2.54,-19.05) AM16(-1.27,-19.05) AM17(0,-19.05) AM18(1.27,-19.05) AM19(2.54,-19.05) AM20(3.81,-19.05) AM21(5.08,-19.05) AM22(6.35,-19.05) AM23(7.62,-19.05) AM24(8.89,-19.05) AM25(10.16,-19.05) AM26(11.43,-19.05) AM27(12.7,-19.05) AM28(13.97,-19.05) AM29(15.24,-19.05) AM30(16.51,-19.05) AM31(17.78,-19.05) AM32(19.05,-19.05) AM33(20.32,-19.05) AN1(-20.32,-20.32) AN2(-19.05,-20.32) AN3(-17.78,-20.32) AN4(-16.51,-20.32) AN5(-15.24,-20.32) AN6(-13.97,-20.32) AN7(-12.7,-20.32) AN8(-11.43,-20.32) AN9(-10.16,-20.32) AN10(-8.89,-20.32) AN11(-7.62,-20.32) AN12(-6.35,-20.32) AN13(-5.08,-20.32) AN14(-3.81,-20.32) AN15(-2.54,-20.32) AN16(-1.27,-20.32) AN17(0,-20.32) AN18(1.27,-20.32) AN19(2.54,-20.32) AN20(3.81,-20.32) AN21(5.08,-20.32) AN22(6.35,-20.32) AN23(7.62,-20.32) AN24(8.89,-20.32) AN25(10.16,-20.32) AN26(11.43,-20.32) AN27(12.7,-20.32) AN28(13.97,-20.32) AN29(15.24,-20.32) AN30(16.51,-20.32) AN31(17.78,-20.32) AN32(19.05,-20.32) AN33(20.32,-20.32) B1(-20.32,19.05) B2(-19.05,19.05) B3(-17.78,19.05) B4(-16.51,19.05) B5(-15.24,19.05) B6(-13.97,19.05) B7(-12.7,19.05) B8(-11.43,19.05) B9(-10.16,19.05) B10(-8.89,19.05) B11(-7.62,19.05) B12(-6.35,19.05) B13(-5.08,19.05) B14(-3.81,19.05) B15(-2.54,19.05) B16(-1.27,19.05) B17(0,19.05) B18(1.27,19.05) B19(2.54,19.05) B20(3.81,19.05) B21(5.08,19.05) B22(6.35,19.05) B23(7.62,19.05) B24(8.89,19.05) B25(10.16,19.05) B26(11.43,19.05) B27(12.7,19.05) B28(13.97,19.05) B29(15.24,19.05) B30(16.51,19.05) B31(17.78,19.05) B32(19.05,19.05) B33(20.32,19.05) C1(-20.32,17.78) C2(-19.05,17.78) C3(-17.78,17.78) C4(-16.51,17.78) C5(-15.24,17.78) C6(-13.97,17.78) C7(-12.7,17.78) C8(-11.43,17.78) C9(-10.16,17.78) C10(-8.89,17.78) C11(-7.62,17.78) C12(-6.35,17.78) C13(-5.08,17.78) C14(-3.81,17.78) C15(-2.54,17.78) C16(-1.27,17.78) C17(0,17.78) C18(1.27,17.78) C19(2.54,17.78) C20(3.81,17.78) C21(5.08,17.78) C22(6.35,17.78) C23(7.62,17.78) C24(8.89,17.78) C25(10.16,17.78) C26(11.43,17.78) C27(12.7,17.78) C28(13.97,17.78) C29(15.24,17.78) C30(16.51,17.78) C31(17.78,17.78) C32(19.05,17.78) C33(20.32,17.78) D1(-20.32,16.51) D2(-19.05,16.51) D3(-17.78,16.51) D4(-16.51,16.51) D5(-15.24,16.51) D6(-13.97,16.51) D7(-12.7,16.51) D8(-11.43,16.51) D9(-10.16,16.51) D10(-8.89,16.51) D11(-7.62,16.51) D12(-6.35,16.51) D13(-5.08,16.51) D14(-3.81,16.51) D15(-2.54,16.51) D16(-1.27,16.51) D17(0,16.51) D18(1.27,16.51) D19(2.54,16.51) D20(3.81,16.51) D21(5.08,16.51) D22(6.35,16.51) D23(7.62,16.51) D24(8.89,16.51) D25(10.16,16.51) D26(11.43,16.51) D27(12.7,16.51) D28(13.97,16.51) D29(15.24,16.51) D30(16.51,16.51) D31(17.78,16.51) D32(19.05,16.51) D33(20.32,16.51) E1(-20.32,15.24) E2(-19.05,15.24) E3(-17.78,15.24) E4(-16.51,15.24) E5(-15.24,15.24) E6(-13.97,15.24) E7(-12.7,15.24) E8(-11.43,15.24) E9(-10.16,15.24) E10(-8.89,15.24) E11(-7.62,15.24) E12(-6.35,15.24) E13(-5.08,15.24) E14(-3.81,15.24) E15(-2.54,15.24) E16(-1.27,15.24) E17(0,15.24) E18(1.27,15.24) E19(2.54,15.24) E20(3.81,15.24) E21(5.08,15.24) E22(6.35,15.24) E23(7.62,15.24) E24(8.89,15.24) E25(10.16,15.24) E26(11.43,15.24) E27(12.7,15.24) E28(13.97,15.24) E29(15.24,15.24) E30(16.51,15.24) E31(17.78,15.24) E32(19.05,15.24) E33(20.32,15.24) F1(-20.32,13.97) F2(-19.05,13.97) F3(-17.78,13.97) F4(-16.51,13.97) F5(-15.24,13.97) F29(15.24,13.97) F30(16.51,13.97) F31(17.78,13.97) F32(19.05,13.97) F33(20.32,13.97) G1(-20.32,12.7) G2(-19.05,12.7) G3(-17.78,12.7) G4(-16.51,12.7) G5(-15.24,12.7) G29(15.24,12.7) G30(16.51,12.7) G31(17.78,12.7) G32(19.05,12.7) G33(20.32,12.7) H1(-20.32,11.43) H2(-19.05,11.43) H3(-17.78,11.43) H4(-16.51,11.43) H5(-15.24,11.43) H29(15.24,11.43) H30(16.51,11.43) H31(17.78,11.43) H32(19.05,11.43) H33(20.32,11.43) J1(-20.32,10.16) J2(-19.05,10.16) J3(-17.78,10.16) J4(-16.51,10.16) J5(-15.24,10.16) J29(15.24,10.16) J30(16.51,10.16) J31(17.78,10.16) J32(19.05,10.16) J33(20.32,10.16) K1(-20.32,8.89) K2(-19.05,8.89) K3(-17.78,8.89) K4(-16.51,8.89) K5(-15.24,8.89) K29(15.24,8.89) K30(16.51,8.89) K31(17.78,8.89) K32(19.05,8.89) K33(20.32,8.89) L1(-20.32,7.62) L2(-19.05,7.62) L3(-17.78,7.62) L4(-16.51,7.62) L5(-15.24,7.62) L29(15.24,7.62) L30(16.51,7.62) L31(17.78,7.62) L32(19.05,7.62) L33(20.32,7.62) M1(-20.32,6.35) M2(-19.05,6.35) M3(-17.78,6.35) M4(-16.51,6.35) M5(-15.24,6.35) M29(15.24,6.35) M30(16.51,6.35) M31(17.78,6.35) M32(19.05,6.35) M33(20.32,6.35) N1(-20.32,5.08) N2(-19.05,5.08) N3(-17.78,5.08) N4(-16.51,5.08) N5(-15.24,5.08) N29(15.24,5.08) N30(16.51,5.08) N31(17.78,5.08) N32(19.05,5.08) N33(20.32,5.08) P1(-20.32,3.81) P2(-19.05,3.81) P3(-17.78,3.81) P4(-16.51,3.81) P5(-15.24,3.81) P29(15.24,3.81) P30(16.51,3.81) P31(17.78,3.81) P32(19.05,3.81) P33(20.32,3.81) R1(-20.32,2.54) R2(-19.05,2.54) R3(-17.78,2.54) R4(-16.51,2.54) R5(-15.24,2.54) R29(15.24,2.54) R30(16.51,2.54) R31(17.78,2.54) R32(19.05,2.54) R33(20.32,2.54) T1(-20.32,1.27) T2(-19.05,1.27) T3(-17.78,1.27) T4(-16.51,1.27) T5(-15.24,1.27) T29(15.24,1.27) T30(16.51,1.27) T31(17.78,1.27) T32(19.05,1.27) T33(20.32,1.27) U1(-20.32,0) U2(-19.05,0) U3(-17.78,0) U4(-16.51,0) U5(-15.24,0) U29(15.24,0) U30(16.51,0) U31(17.78,0) U32(19.05,0) U33(20.32,0) V1(-20.32,-1.27) V2(-19.05,-1.27) V3(-17.78,-1.27) V4(-16.51,-1.27) V5(-15.24,-1.27) V29(15.24,-1.27) V30(16.51,-1.27) V31(17.78,-1.27) V32(19.05,-1.27) V33(20.32,-1.27) W1(-20.32,-2.54) W2(-19.05,-2.54) W3(-17.78,-2.54) W4(-16.51,-2.54) W5(-15.24,-2.54) W29(15.24,-2.54) W30(16.51,-2.54) W31(17.78,-2.54) W32(19.05,-2.54) W33(20.32,-2.54) Y1(-20.32,-3.81) Y2(-19.05,-3.81) Y3(-17.78,-3.81) Y4(-16.51,-3.81) Y5(-15.24,-3.81) Y29(15.24,-3.81) Y30(16.51,-3.81) Y31(17.78,-3.81) Y32(19.05,-3.81) Y33(20.32,-3.81)
Top Overlay:
  circle w0.25: c-21.9,20.32 r0.125
  region: -20.557,21.25 -21.25,20.557 -21.25,21.25
  lines w0.2: -21.25,20.557 -20.557,21.25 ; -21.25,-21.25 -21.25,21.25 21.25,21.25 21.25,-21.25 -21.25,-21.25
Mechanical 13:
  lines w0.1: -21.25,-21.25 -21.25,21.25 21.25,21.25 21.25,-21.25 -21.25,-21.25
Mechanical 15:
  lines w0.1: -0.5,0 0.5,0 ; 0,-0.5 0,0.5 ; -22.25,-22.25 -22.25,22.25 22.25,22.25 22.25,-22.25 -22.25,-22.25
3D body: height 5.35, standoff 0, extent -21.25,-21.25 21.25,21.25

## CG717 [mm] "729-Pin Ceramic Column Grid Array 1.27 mm Pitch"
height 5.5
pads (717):
  round 0.55 smd: A3(-13.97,16.51) A4(-12.7,16.51) A5(-11.43,16.51) A6(-10.16,16.51) A7(-8.89,16.51) A8(-7.62,16.51) A9(-6.35,16.51) A10(-5.08,16.51) A11(-3.81,16.51) A12(-2.54,16.51) A13(-1.27,16.51) A14(0,16.51) A15(1.27,16.51) A16(2.54,16.51) A17(3.81,16.51) A18(5.08,16.51) A19(6.35,16.51) A20(7.62,16.51) A21(8.89,16.51) A22(10.16,16.51) A23(11.43,16.51) A24(12.7,16.51) A25(13.97,16.51) AA1(-16.51,-8.89) AA2(-15.24,-8.89) AA3(-13.97,-8.89) AA4(-12.7,-8.89) AA5(-11.43,-8.89) AA6(-10.16,-8.89) AA7(-8.89,-8.89) AA8(-7.62,-8.89) AA9(-6.35,-8.89) AA10(-5.08,-8.89) AA11(-3.81,-8.89) AA12(-2.54,-8.89) AA13(-1.27,-8.89) AA14(0,-8.89) AA15(1.27,-8.89) AA16(2.54,-8.89) AA17(3.81,-8.89) AA18(5.08,-8.89) AA19(6.35,-8.89) AA20(7.62,-8.89) AA21(8.89,-8.89) AA22(10.16,-8.89) AA23(11.43,-8.89) AA24(12.7,-8.89) AA25(13.97,-8.89) AA26(15.24,-8.89) AA27(16.51,-8.89) AB1(-16.51,-10.16) AB2(-15.24,-10.16) AB3(-13.97,-10.16) AB4(-12.7,-10.16) AB5(-11.43,-10.16) AB6(-10.16,-10.16) AB7(-8.89,-10.16) AB8(-7.62,-10.16) AB9(-6.35,-10.16) AB10(-5.08,-10.16) AB11(-3.81,-10.16) AB12(-2.54,-10.16) AB13(-1.27,-10.16) AB14(0,-10.16) AB15(1.27,-10.16) AB16(2.54,-10.16) AB17(3.81,-10.16) AB18(5.08,-10.16) AB19(6.35,-10.16) AB20(7.62,-10.16) AB21(8.89,-10.16) AB22(10.16,-10.16) AB23(11.43,-10.16) AB24(12.7,-10.16) AB25(13.97,-10.16) AB26(15.24,-10.16) AB27(16.51,-10.16) AC1(-16.51,-11.43) AC2(-15.24,-11.43) AC3(-13.97,-11.43) AC4(-12.7,-11.43) AC5(-11.43,-11.43) AC6(-10.16,-11.43) AC7(-8.89,-11.43) AC8(-7.62,-11.43) AC9(-6.35,-11.43) AC10(-5.08,-11.43) AC11(-3.81,-11.43) AC12(-2.54,-11.43) AC13(-1.27,-11.43) AC14(0,-11.43) AC15(1.27,-11.43) AC16(2.54,-11.43) AC17(3.81,-11.43) AC18(5.08,-11.43) AC19(6.35,-11.43) AC20(7.62,-11.43) AC21(8.89,-11.43) AC22(10.16,-11.43) AC23(11.43,-11.43) AC24(12.7,-11.43) AC25(13.97,-11.43) AC26(15.24,-11.43) AC27(16.51,-11.43) AD1(-16.51,-12.7) AD2(-15.24,-12.7) AD3(-13.97,-12.7) AD4(-12.7,-12.7) AD5(-11.43,-12.7) AD6(-10.16,-12.7) AD7(-8.89,-12.7) AD8(-7.62,-12.7) AD9(-6.35,-12.7) AD10(-5.08,-12.7) AD11(-3.81,-12.7) AD12(-2.54,-12.7) AD13(-1.27,-12.7) AD14(0,-12.7) AD15(1.27,-12.7) AD16(2.54,-12.7) AD17(3.81,-12.7) AD18(5.08,-12.7) AD19(6.35,-12.7) AD20(7.62,-12.7) AD21(8.89,-12.7) AD22(10.16,-12.7) AD23(11.43,-12.7) AD24(12.7,-12.7) AD25(13.97,-12.7) AD26(15.24,-12.7) AD27(16.51,-12.7) AE1(-16.51,-13.97) AE2(-15.24,-13.97) AE3(-13.97,-13.97) AE4(-12.7,-13.97) AE5(-11.43,-13.97) AE6(-10.16,-13.97) AE7(-8.89,-13.97) AE8(-7.62,-13.97) AE9(-6.35,-13.97) AE10(-5.08,-13.97) AE11(-3.81,-13.97) AE12(-2.54,-13.97) AE13(-1.27,-13.97) AE14(0,-13.97) AE15(1.27,-13.97) AE16(2.54,-13.97) AE17(3.81,-13.97) AE18(5.08,-13.97) AE19(6.35,-13.97) AE20(7.62,-13.97) AE21(8.89,-13.97) AE22(10.16,-13.97) AE23(11.43,-13.97) AE24(12.7,-13.97) AE25(13.97,-13.97) AE26(15.24,-13.97) AE27(16.51,-13.97) AF2(-15.24,-15.24) AF3(-13.97,-15.24) AF4(-12.7,-15.24) AF5(-11.43,-15.24) AF6(-10.16,-15.24) AF7(-8.89,-15.24) AF8(-7.62,-15.24) AF9(-6.35,-15.24) AF10(-5.08,-15.24) AF11(-3.81,-15.24) AF12(-2.54,-15.24) AF13(-1.27,-15.24) AF14(0,-15.24) AF15(1.27,-15.24) AF16(2.54,-15.24) AF17(3.81,-15.24) AF18(5.08,-15.24) AF19(6.35,-15.24) AF20(7.62,-15.24) AF21(8.89,-15.24) AF22(10.16,-15.24) AF23(11.43,-15.24) AF24(12.7,-15.24) AF25(13.97,-15.24) AF26(15.24,-15.24) AG3(-13.97,-16.51) AG4(-12.7,-16.51) AG5(-11.43,-16.51) AG6(-10.16,-16.51) AG7(-8.89,-16.51) AG8(-7.62,-16.51) AG9(-6.35,-16.51) AG10(-5.08,-16.51) AG11(-3.81,-16.51) AG12(-2.54,-16.51) AG13(-1.27,-16.51) AG14(0,-16.51) AG15(1.27,-16.51) AG16(2.54,-16.51) AG17(3.81,-16.51) AG18(5.08,-16.51) AG19(6.35,-16.51) AG20(7.62,-16.51) AG21(8.89,-16.51) AG22(10.16,-16.51) AG23(11.43,-16.51) AG24(12.7,-16.51) AG25(13.97,-16.51) B2(-15.24,15.24) B3(-13.97,15.24) B4(-12.7,15.24) B5(-11.43,15.24) B6(-10.16,15.24) B7(-8.89,15.24) B8(-7.62,15.24) B9(-6.35,15.24) B10(-5.08,15.24) B11(-3.81,15.24) B12(-2.54,15.24) B13(-1.27,15.24) B14(0,15.24) B15(1.27,15.24) B16(2.54,15.24) B17(3.81,15.24) B18(5.08,15.24) B19(6.35,15.24) B20(7.62,15.24) B21(8.89,15.24) B22(10.16,15.24) B23(11.43,15.24) B24(12.7,15.24) B25(13.97,15.24) B26(15.24,15.24) C1(-16.51,13.97) C2(-15.24,13.97) C3(-13.97,13.97) C4(-12.7,13.97) C5(-11.43,13.97) C6(-10.16,13.97) C7(-8.89,13.97) C8(-7.62,13.97) C9(-6.35,13.97) C10(-5.08,13.97) C11(-3.81,13.97) C12(-2.54,13.97) C13(-1.27,13.97) C14(0,13.97) C15(1.27,13.97) C16(2.54,13.97) C17(3.81,13.97) C18(5.08,13.97) C19(6.35,13.97) C20(7.62,13.97) C21(8.89,13.97) C22(10.16,13.97) C23(11.43,13.97) C24(12.7,13.97) C25(13.97,13.97) C26(15.24,13.97) C27(16.51,13.97) D1(-16.51,12.7) D2(-15.24,12.7) D3(-13.97,12.7) D4(-12.7,12.7) D5(-11.43,12.7) D6(-10.16,12.7) D7(-8.89,12.7) D8(-7.62,12.7) D9(-6.35,12.7) D10(-5.08,12.7) D11(-3.81,12.7) D12(-2.54,12.7) D13(-1.27,12.7) D14(0,12.7) D15(1.27,12.7) D16(2.54,12.7) D17(3.81,12.7) D18(5.08,12.7) D19(6.35,12.7) D20(7.62,12.7) D21(8.89,12.7) D22(10.16,12.7) D23(11.43,12.7) D24(12.7,12.7) D25(13.97,12.7) D26(15.24,12.7) D27(16.51,12.7) E1(-16.51,11.43) E2(-15.24,11.43) E3(-13.97,11.43) E4(-12.7,11.43) E5(-11.43,11.43) E6(-10.16,11.43) E7(-8.89,11.43) E8(-7.62,11.43) E9(-6.35,11.43) E10(-5.08,11.43) E11(-3.81,11.43) E12(-2.54,11.43) E13(-1.27,11.43) E14(0,11.43) E15(1.27,11.43) E16(2.54,11.43) E17(3.81,11.43) E18(5.08,11.43) E19(6.35,11.43) E20(7.62,11.43) E21(8.89,11.43) E22(10.16,11.43) E23(11.43,11.43) E24(12.7,11.43) E25(13.97,11.43) E26(15.24,11.43) E27(16.51,11.43) F1(-16.51,10.16) F2(-15.24,10.16) F3(-13.97,10.16) F4(-12.7,10.16) F5(-11.43,10.16) F6(-10.16,10.16) F7(-8.89,10.16) F8(-7.62,10.16) F9(-6.35,10.16) F10(-5.08,10.16) F11(-3.81,10.16) F12(-2.54,10.16) F13(-1.27,10.16) F14(0,10.16) F15(1.27,10.16) F16(2.54,10.16) F17(3.81,10.16) F18(5.08,10.16) F19(6.35,10.16) F20(7.62,10.16) F21(8.89,10.16) F22(10.16,10.16) F23(11.43,10.16) F24(12.7,10.16) F25(13.97,10.16) F26(15.24,10.16) F27(16.51,10.16) G1(-16.51,8.89) G2(-15.24,8.89) G3(-13.97,8.89) G4(-12.7,8.89) G5(-11.43,8.89) G6(-10.16,8.89) G7(-8.89,8.89) G8(-7.62,8.89) G9(-6.35,8.89) G10(-5.08,8.89) G11(-3.81,8.89) G12(-2.54,8.89) G13(-1.27,8.89) G14(0,8.89) G15(1.27,8.89) G16(2.54,8.89) G17(3.81,8.89) G18(5.08,8.89) G19(6.35,8.89) G20(7.62,8.89) G21(8.89,8.89) G22(10.16,8.89) G23(11.43,8.89) G24(12.7,8.89) G25(13.97,8.89) G26(15.24,8.89) G27(16.51,8.89) H1(-16.51,7.62) H2(-15.24,7.62) H3(-13.97,7.62) H4(-12.7,7.62) H5(-11.43,7.62) H6(-10.16,7.62) H7(-8.89,7.62) H8(-7.62,7.62) H9(-6.35,7.62) H10(-5.08,7.62) H11(-3.81,7.62) H12(-2.54,7.62) H13(-1.27,7.62) H14(0,7.62) H15(1.27,7.62) H16(2.54,7.62) H17(3.81,7.62) H18(5.08,7.62) H19(6.35,7.62) H20(7.62,7.62) H21(8.89,7.62) H22(10.16,7.62) H23(11.43,7.62) H24(12.7,7.62) H25(13.97,7.62) H26(15.24,7.62) H27(16.51,7.62) J1(-16.51,6.35) J2(-15.24,6.35) J3(-13.97,6.35) J4(-12.7,6.35) J5(-11.43,6.35) J6(-10.16,6.35) J7(-8.89,6.35) J8(-7.62,6.35) J9(-6.35,6.35) J10(-5.08,6.35) J11(-3.81,6.35) J12(-2.54,6.35) J13(-1.27,6.35) J14(0,6.35) J15(1.27,6.35) J16(2.54,6.35) J17(3.81,6.35) J18(5.08,6.35) J19(6.35,6.35) J20(7.62,6.35) J21(8.89,6.35) J22(10.16,6.35) J23(11.43,6.35) J24(12.7,6.35) J25(13.97,6.35) J26(15.24,6.35) J27(16.51,6.35) K1(-16.51,5.08) K2(-15.24,5.08) K3(-13.97,5.08) K4(-12.7,5.08) K5(-11.43,5.08) K6(-10.16,5.08) K7(-8.89,5.08) K8(-7.62,5.08) K9(-6.35,5.08) K10(-5.08,5.08) K11(-3.81,5.08) K12(-2.54,5.08) K13(-1.27,5.08) K14(0,5.08) K15(1.27,5.08) K16(2.54,5.08) K17(3.81,5.08) K18(5.08,5.08) K19(6.35,5.08) K20(7.62,5.08) K21(8.89,5.08) K22(10.16,5.08) K23(11.43,5.08) K24(12.7,5.08) K25(13.97,5.08) K26(15.24,5.08) K27(16.51,5.08) L1(-16.51,3.81) L2(-15.24,3.81) L3(-13.97,3.81) L4(-12.7,3.81) L5(-11.43,3.81) L6(-10.16,3.81) L7(-8.89,3.81) L8(-7.62,3.81) L9(-6.35,3.81) L10(-5.08,3.81) L11(-3.81,3.81) L12(-2.54,3.81) L13(-1.27,3.81) L14(0,3.81) L15(1.27,3.81) L16(2.54,3.81) L17(3.81,3.81) L18(5.08,3.81) L19(6.35,3.81) L20(7.62,3.81) L21(8.89,3.81) L22(10.16,3.81) L23(11.43,3.81) L24(12.7,3.81) L25(13.97,3.81) L26(15.24,3.81) L27(16.51,3.81) M1(-16.51,2.54) M2(-15.24,2.54) M3(-13.97,2.54) M4(-12.7,2.54) M5(-11.43,2.54) M6(-10.16,2.54) M7(-8.89,2.54) M8(-7.62,2.54) M9(-6.35,2.54) M10(-5.08,2.54) M11(-3.81,2.54) M12(-2.54,2.54) M13(-1.27,2.54) M14(0,2.54) M15(1.27,2.54) M16(2.54,2.54) M17(3.81,2.54) M18(5.08,2.54) M19(6.35,2.54) M20(7.62,2.54) M21(8.89,2.54) M22(10.16,2.54) M23(11.43,2.54) M24(12.7,2.54) M25(13.97,2.54) M26(15.24,2.54) M27(16.51,2.54) N1(-16.51,1.27) N2(-15.24,1.27) N3(-13.97,1.27) N4(-12.7,1.27) N5(-11.43,1.27) N6(-10.16,1.27) N7(-8.89,1.27) N8(-7.62,1.27) N9(-6.35,1.27) N10(-5.08,1.27) N11(-3.81,1.27) N12(-2.54,1.27) N13(-1.27,1.27) N14(0,1.27) N15(1.27,1.27) N16(2.54,1.27) N17(3.81,1.27) N18(5.08,1.27) N19(6.35,1.27) N20(7.62,1.27) N21(8.89,1.27) N22(10.16,1.27) N23(11.43,1.27) N24(12.7,1.27) N25(13.97,1.27) N26(15.24,1.27) N27(16.51,1.27) P1(-16.51,0) P2(-15.24,0) P3(-13.97,0) P4(-12.7,0) P5(-11.43,0) P6(-10.16,0) P7(-8.89,0) P8(-7.62,0) P9(-6.35,0) P10(-5.08,0) P11(-3.81,0) P12(-2.54,0) P13(-1.27,0) P14(0,0) P15(1.27,0) P16(2.54,0) P17(3.81,0) P18(5.08,0) P19(6.35,0) P20(7.62,0) P21(8.89,0) P22(10.16,0) P23(11.43,0) P24(12.7,0) P25(13.97,0) P26(15.24,0) P27(16.51,0) R1(-16.51,-1.27) R2(-15.24,-1.27) R3(-13.97,-1.27) R4(-12.7,-1.27) R5(-11.43,-1.27) R6(-10.16,-1.27) R7(-8.89,-1.27) R8(-7.62,-1.27) R9(-6.35,-1.27) R10(-5.08,-1.27) R11(-3.81,-1.27) R12(-2.54,-1.27) R13(-1.27,-1.27) R14(0,-1.27) R15(1.27,-1.27) R16(2.54,-1.27) R17(3.81,-1.27) R18(5.08,-1.27) R19(6.35,-1.27) R20(7.62,-1.27) R21(8.89,-1.27) R22(10.16,-1.27) R23(11.43,-1.27) R24(12.7,-1.27) R25(13.97,-1.27) R26(15.24,-1.27) R27(16.51,-1.27) T1(-16.51,-2.54) T2(-15.24,-2.54) T3(-13.97,-2.54) T4(-12.7,-2.54) T5(-11.43,-2.54) T6(-10.16,-2.54) T7(-8.89,-2.54) T8(-7.62,-2.54) T9(-6.35,-2.54) T10(-5.08,-2.54) T11(-3.81,-2.54) T12(-2.54,-2.54) T13(-1.27,-2.54) T14(0,-2.54) T15(1.27,-2.54) T16(2.54,-2.54) T17(3.81,-2.54) T18(5.08,-2.54) T19(6.35,-2.54) T20(7.62,-2.54) T21(8.89,-2.54) T22(10.16,-2.54) T23(11.43,-2.54) T24(12.7,-2.54) T25(13.97,-2.54) T26(15.24,-2.54) T27(16.51,-2.54) U1(-16.51,-3.81) U2(-15.24,-3.81) U3(-13.97,-3.81) U4(-12.7,-3.81) U5(-11.43,-3.81) U6(-10.16,-3.81) U7(-8.89,-3.81) U8(-7.62,-3.81) U9(-6.35,-3.81) U10(-5.08,-3.81) U11(-3.81,-3.81) U12(-2.54,-3.81) U13(-1.27,-3.81) U14(0,-3.81) U15(1.27,-3.81) U16(2.54,-3.81) U17(3.81,-3.81) U18(5.08,-3.81) U19(6.35,-3.81) U20(7.62,-3.81) U21(8.89,-3.81) U22(10.16,-3.81) U23(11.43,-3.81) U24(12.7,-3.81) U25(13.97,-3.81) U26(15.24,-3.81) U27(16.51,-3.81) V1(-16.51,-5.08) V2(-15.24,-5.08) V3(-13.97,-5.08) V4(-12.7,-5.08) V5(-11.43,-5.08) V6(-10.16,-5.08) V7(-8.89,-5.08) V8(-7.62,-5.08) V9(-6.35,-5.08) V10(-5.08,-5.08) V11(-3.81,-5.08) V12(-2.54,-5.08) V13(-1.27,-5.08) V14(0,-5.08) V15(1.27,-5.08) V16(2.54,-5.08) V17(3.81,-5.08) V18(5.08,-5.08) V19(6.35,-5.08) V20(7.62,-5.08) V21(8.89,-5.08) V22(10.16,-5.08) V23(11.43,-5.08) V24(12.7,-5.08) V25(13.97,-5.08) V26(15.24,-5.08) V27(16.51,-5.08) W1(-16.51,-6.35) W2(-15.24,-6.35) W3(-13.97,-6.35) W4(-12.7,-6.35) W5(-11.43,-6.35) W6(-10.16,-6.35) W7(-8.89,-6.35) W8(-7.62,-6.35) W9(-6.35,-6.35) W10(-5.08,-6.35) W11(-3.81,-6.35) W12(-2.54,-6.35) W13(-1.27,-6.35) W14(0,-6.35) W15(1.27,-6.35) W16(2.54,-6.35) W17(3.81,-6.35) W18(5.08,-6.35) W19(6.35,-6.35) W20(7.62,-6.35) W21(8.89,-6.35) W22(10.16,-6.35) W23(11.43,-6.35) W24(12.7,-6.35) W25(13.97,-6.35) W26(15.24,-6.35) W27(16.51,-6.35) Y1(-16.51,-7.62) Y2(-15.24,-7.62) Y3(-13.97,-7.62) Y4(-12.7,-7.62) Y5(-11.43,-7.62) Y6(-10.16,-7.62) Y7(-8.89,-7.62) Y8(-7.62,-7.62) Y9(-6.35,-7.62) Y10(-5.08,-7.62) Y11(-3.81,-7.62) Y12(-2.54,-7.62) Y13(-1.27,-7.62) Y14(0,-7.62) Y15(1.27,-7.62) Y16(2.54,-7.62) Y17(3.81,-7.62) Y18(5.08,-7.62) Y19(6.35,-7.62) Y20(7.62,-7.62) Y21(8.89,-7.62) Y22(10.16,-7.62) Y23(11.43,-7.62) Y24(12.7,-7.62) Y25(13.97,-7.62) Y26(15.24,-7.62) Y27(16.51,-7.62)
Top Overlay:
  circle w0.25: c-18.16,16.51 r0.125
  region: -16.51,17.51 -17.51,16.51 -17.51,17.51
  lines w0.2: -17.51,16.51 -16.51,17.51 ; -17.51,-17.49 17.49,-17.49 17.49,17.51 -17.51,17.51 -17.51,-17.49
Mechanical 13:
  lines w0.1: -17.51,-17.49 17.49,-17.49 17.49,17.51 -17.51,17.51 -17.51,-17.49
Mechanical 15:
  lines w0.1: -0.51,0.01 0.49,0.01 ; -0.01,-0.49 -0.01,0.51 ; -18.51,-18.49 18.49,-18.49 18.49,18.51 -18.51,18.51 -18.51,-18.49
3D body: height 5.5, standoff 0, extent -17.51,-17.49 17.49,17.51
